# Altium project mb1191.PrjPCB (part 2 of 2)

## Sheet USB_OTG_HS.SchDoc: USB OTG HS PHY with Micro A-B connector
size A4; Date: 25-FEB-2015; Author: A.B; CompanyName: STMicroelectronics; Address1: 12, Rue Jules HOROWITZ; Address2: 38019 Grenoble; Address3: FRANCE; DocumentNumber: MB1191; Revision: B-02; SheetNumber: 11; SheetTotal: 14; Project: STM32F746G-DISCO
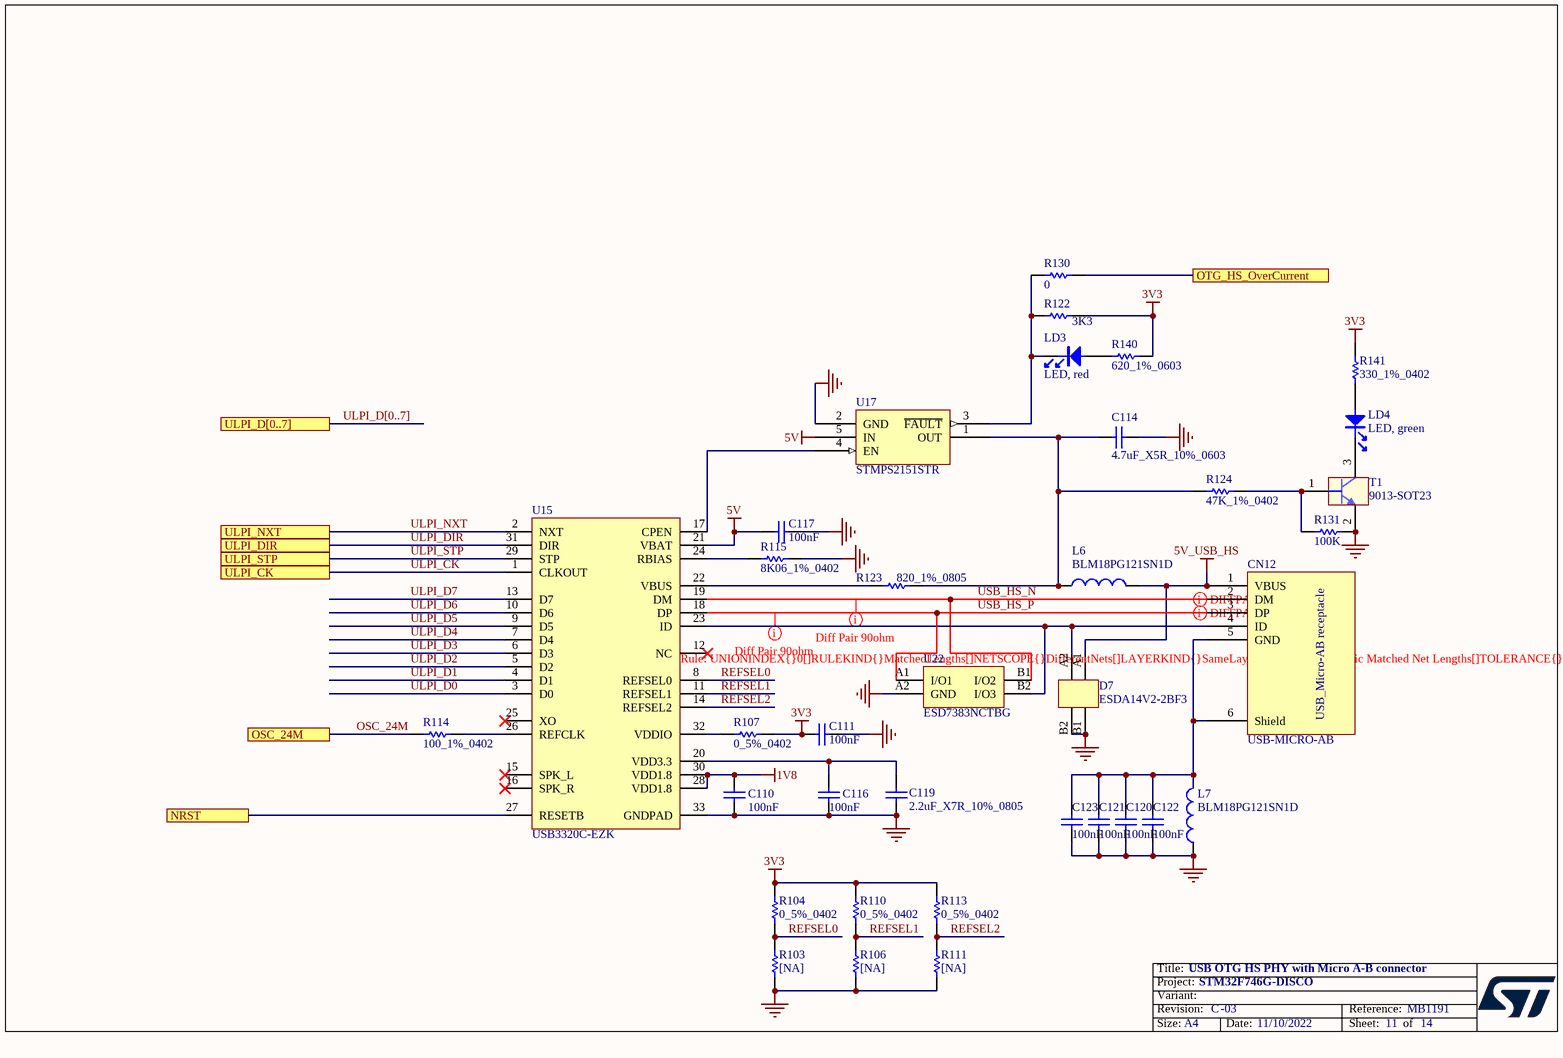
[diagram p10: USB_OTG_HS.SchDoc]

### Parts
C110  100nF  [0402C]
C111  100nF  [0402C]
C114  4.7uF_X5R_10%_0603  [0603C]
C116  100nF  [0402C]
C117  100nF  [0402C]
C119  2.2uF_X7R_10%_0805  [0805C]
C120  100nF  [0402C]
C121  100nF  [0402C]
C122  100nF  [0402C]
C123  100nF  [0402C]
CN12  USB-MICRO-AB  [USB-MICRO-AB]
D7  ESDA14V2-2BF3  [BGA4_1X1]
L6  BLM18PG121SN1D  [0603L]
L7  BLM18PG121SN1D  [0603L]
LD3  LED, red  [0603D]
LD4  LED, green  [0603D]
R103  [NA]  [0402R]
R104  0_5%_0402  [0402R]
R106  [NA]  [0402R]
R107  0_5%_0402  [0402R]
R110  0_5%_0402  [0402R]
R111  [NA]  [0402R]
R113  0_5%_0402  [0402R]
R114  100_1%_0402  [0402R]
R115  8K06_1%_0402  [0402R]
R122  3K3  [0402R]
R123  820_1%_0805  [0805R]
R124  47K_1%_0402  [0402R]
R130  0  [0402R]
R131  100K  [0402R]
R140  620_1%_0603  [0603R]
R141  330_1%_0402  [0402R]
T1  9013-SOT23  [SOT23]
U15  USB3320C-EZK  [QFN32_0R5_5X5]
U17  STMPS2151STR  [SOT23-5L]
U22  ESD7383NCTBG  [ESD_WLCSP4_CASE-567CB_0P80X0P80_P040]

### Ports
NRST, OSC_24M, OTG_HS_OverCurrent, ULPI_CK, ULPI_D[0..7], ULPI_DIR, ULPI_NXT, ULPI_STP

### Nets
1V8: C110.2 U15.28(VDD1.8) U15.30(VDD1.8)
3V3: C111.1 R104.2 R107.2 R110.2 R113.2 R122.1 R140.2 R141.2
5V: C117.1 U15.21(VBAT) U17.5(IN)
5V_USB_HS: CN12.1(VBUS) D7.A1 L6.2
GND: C110.1 C111.2 C114.2 C116.1 C117.2 C119.1 C120.1 C121.1 C122.1 C123.1 D7.B1 D7.B2 L7.1 R103.1 R106.1 R111.1 R115.2 R131.2 T1.2(E) U15.33(GNDPAD) U17.2(GND) U22.A2(GND)
DCMI_NRST: U15.27(RESETB) ; port NRST
OSC_24M: R114.1 ; port OSC_24M
OTG_HS_OverCurrent: R130.2 ; port OTG_HS_OverCurrent
REFSEL0: R103.2 R104.1 U15.8(REFSEL0)
REFSEL1: R106.2 R110.1 U15.11(REFSEL1)
REFSEL2: R111.2 R113.1 U15.14(REFSEL2)
ULPI_CK: U15.1(CLKOUT) ; port ULPI_CK  [project net PA5]
ULPI_D0: U15.3(D0)  [project net PA3]
ULPI_D1: U15.4(D1)  [project net PB0]
ULPI_D2: U15.5(D2)  [project net PB1]
ULPI_D3: U15.6(D3)  [project net PB10]
ULPI_D4: U15.7(D4)  [project net PB11]
ULPI_D5: U15.9(D5)  [project net PB12]
ULPI_D6: U15.10(D6)  [project net PB13]
ULPI_D7: U15.13(D7)  [project net PB5]
ULPI_DIR: U15.31(DIR) ; port ULPI_DIR  [project net PC2]
ULPI_NXT: U15.2(NXT) ; port ULPI_NXT  [project net PH4]
ULPI_STP: U15.29(STP) ; port ULPI_STP  [project net PC0]
USB_HS_N: CN12.2(DM) U15.19(DM) U22.B1(I/O2)
USB_HS_P: CN12.3(DP) U15.18(DP) U22.A1(I/O1)
NetC114_1: C114.1 L6.1 R123.2 R124.1 U17.1(OUT)
NetC116_2: C116.2 C119.2 U15.20(VDD3.3)
NetC120_2: C120.2 C121.2 C122.2 C123.2 CN12.5(GND) CN12.6(Shield) L7.2
NetCN12_4: CN12.4(ID) D7.A2 U15.23(ID) U22.B2(I/O3)
NetLD3_1: LD3.1 R140.1
NetLD3_2: LD3.2 R122.2 R130.1 U17.3(~{FAULT})
NetLD4_1: LD4.1 R141.1
NetLD4_2: LD4.2 T1.3(C)
NetR107_1: R107.1 U15.32(VDDIO)
NetR114_2: R114.2 U15.26(REFCLK)
NetR115_1: R115.1 U15.24(RBIAS)
NetR123_1: R123.1 U15.22(VBUS)
NetR124_2: R124.2 R131.1 T1.1(B)
NetU15_17: U15.17(CPEN) U17.4(EN)

Not connected (* = marked no-connect by the designer): U15 12(NC)* 15(SPK_L)* 16(SPK_R)* 25(XO)*

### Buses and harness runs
bus ULPI_D[0..7] = port ULPI_D[0..7]

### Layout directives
differential pair: USB_HS_N, USB_HS_P
rule Matched Net Lengths [Tolerance = 150mil]: USB_HS_N, USB_HS_P

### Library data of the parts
C110 C111 C116 C117 C120-C123 = Cap_100nF_X7R_10%_0402: Capacitor,100nF,16V,X7R,10%,0402,YAGEO; Manuf_Part_1: CC0402KRX7R7BB104
C114 = Cap_4.7uF_X5R_10%_0603: Capacitor,4.7uF,16V, X5R,10%,0603,YAGEO; Manuf_Part_1: CC0603KRX5R7BB475; Order: CC0603KRX5R7BB105
C119 = Cap_2.2uF_X7R_10%_0805: Capacitor,2.2uF,16V, X7R,10%,0805,YAGEO; Manuf_Part_1: CC0805KKX7R7BB225
CN12 = USB-MICRO-AB: USB-MICRO-AB, 47590-0001, SMT, MOLEX; Ref St: xxxxxxx
D7 = ESDA14V2-2BF3: Quad bidirectional Transil array for ESD protection; Manuf_1: STM; ECCN_US/EU: EAR99/NEC; Provided: ST; Ref St: 9179040
L6 L7 = BEAD_120R_2A_0603: Bead,120R,2A,0603,BLM18PG121SN1D,MURATA; Manuf_Part_3: FCM1608KF-601T03; Manuf_2: TDK; Manuf_Part_2: MPZ1608S300A; Manuf_3: Tai-tech; Value: 100uH; Description_3: Bead,600R,350mA,0603,FCM1608KF-601T03,Tai-tech; Description_2: Bead,30R,5A,0603,MPZ1608S300A,TDK
LD3 = LED_red: LED, red, 0603; Manuf_1: everlight; Manuf_Part_1: 19-217/R6C-AL1M2VY/3T; ECCN_US/EU: EAR99/NEC
LD4 = LED_green: LED, green, 0603; Manuf_1: everlight; Manuf_Part_1: 19-213SYGC/S530-E2/TR8; ECCN_US/EU: EAR99/NEC
R103 R106 R111 = Res_NA_0402: Resistor,[NA],0402; Fitted: NO
R104 R107 R110 R113 = Res_0_5%_0402: Resistor,0,0402,5%,YAGEO; Manuf_Part_1: RC0402JR-070RL; Value: 0; Order: 2363467
R114 = Res_100_1%_0402: Resistor,100,0402,1%,YAGEO; Manuf_Part_1: RC0402FR-07100RL; Value: 100; Order: 9239111
R115 = Res_8K06_1%_0402: Resistor,8K06,0402,1%,YAGEO; Manuf_Part_1: RC0402FR-078K06L
R122 = Res_3K3_1%_0402: Resistor,3K3,0402,1%,YAGEO; Manuf_Part_1: RC0402FR-073K3L
R123 = Res_820_1%_0805: Resistor,820,0805,1%,YAGEO; Manuf_Part_1: RC0805FR-07820RL; Value: 820
R124 = Res_47K_1%_0402: Resistor,47K,0402,1%,YAGEO; Manuf_Part_1: RC0402FR-0747KL; Order: 9239430
R130 = Res_0_5%_0402: Resistor,0,0402,5%,YAGEO; Manuf_Part_1: RC0402JR-070RL; Order: 2363467
R131 = Res_100K_1%_0402: Resistor,100K,0402,1%,YAGEO; Manuf_Part_1: RT0402FRE07100KL
R140 = Res_620_1%_0603: Resistor,620,0603,1%,VISHAY; Manuf_Part_1: CRCW0603620RFKEA; Manuf_1: VISHAY DRALORIC; Value: 620; Order: 2122341
R141 = Res_330_1%_0402: Resistor,330,0402,1%,YAGEO; Manuf_Part_1: RC0402FR-07330RL; Value: 330
T1 = 9013-SOT23: NPN Bipolar Transistor; Manuf_1: NXP; Manuf_Part_1: BSR14; Order: 1081310; ECCN_US/EU: EAR99/NEC
U15 = USB3320C-EZK: USB3320C,  Hi-Speed USB Host, Device or OTG PHY with ULPI Low Pin Interface; Manuf_1: MICROCHIP; Manuf_Part_1: USB3320C-EZK-TR
U17 = STMPS2151STR: Enhanced single channel power switches; Manuf_1: STM; Provided: ST; ECCN_US/EU: EAR99/NEC; Ref St: xxxxxx
U22 = ESD7383NCTBG: 3-line low capacitance protection for high speed USB; Manuf_1: ON SEMICONDUCTOR; ECCN_US/EU: EAR99/NEC; provided: SUBCO

## Sheet STM32F7.SchDoc: STM32 MCU Connexion
size A3; Date: 25-FEB-2015; Author: A.B; CompanyName: STMicroelectronics; Address1: 12, Rue Jules HOROWITZ; Address2: 38019 Grenoble; Address3: FRANCE; DocumentNumber: MB1191; Revision: B-02; SheetNumber: 3; SheetTotal: 14; Project: STM32F746G-DISCO
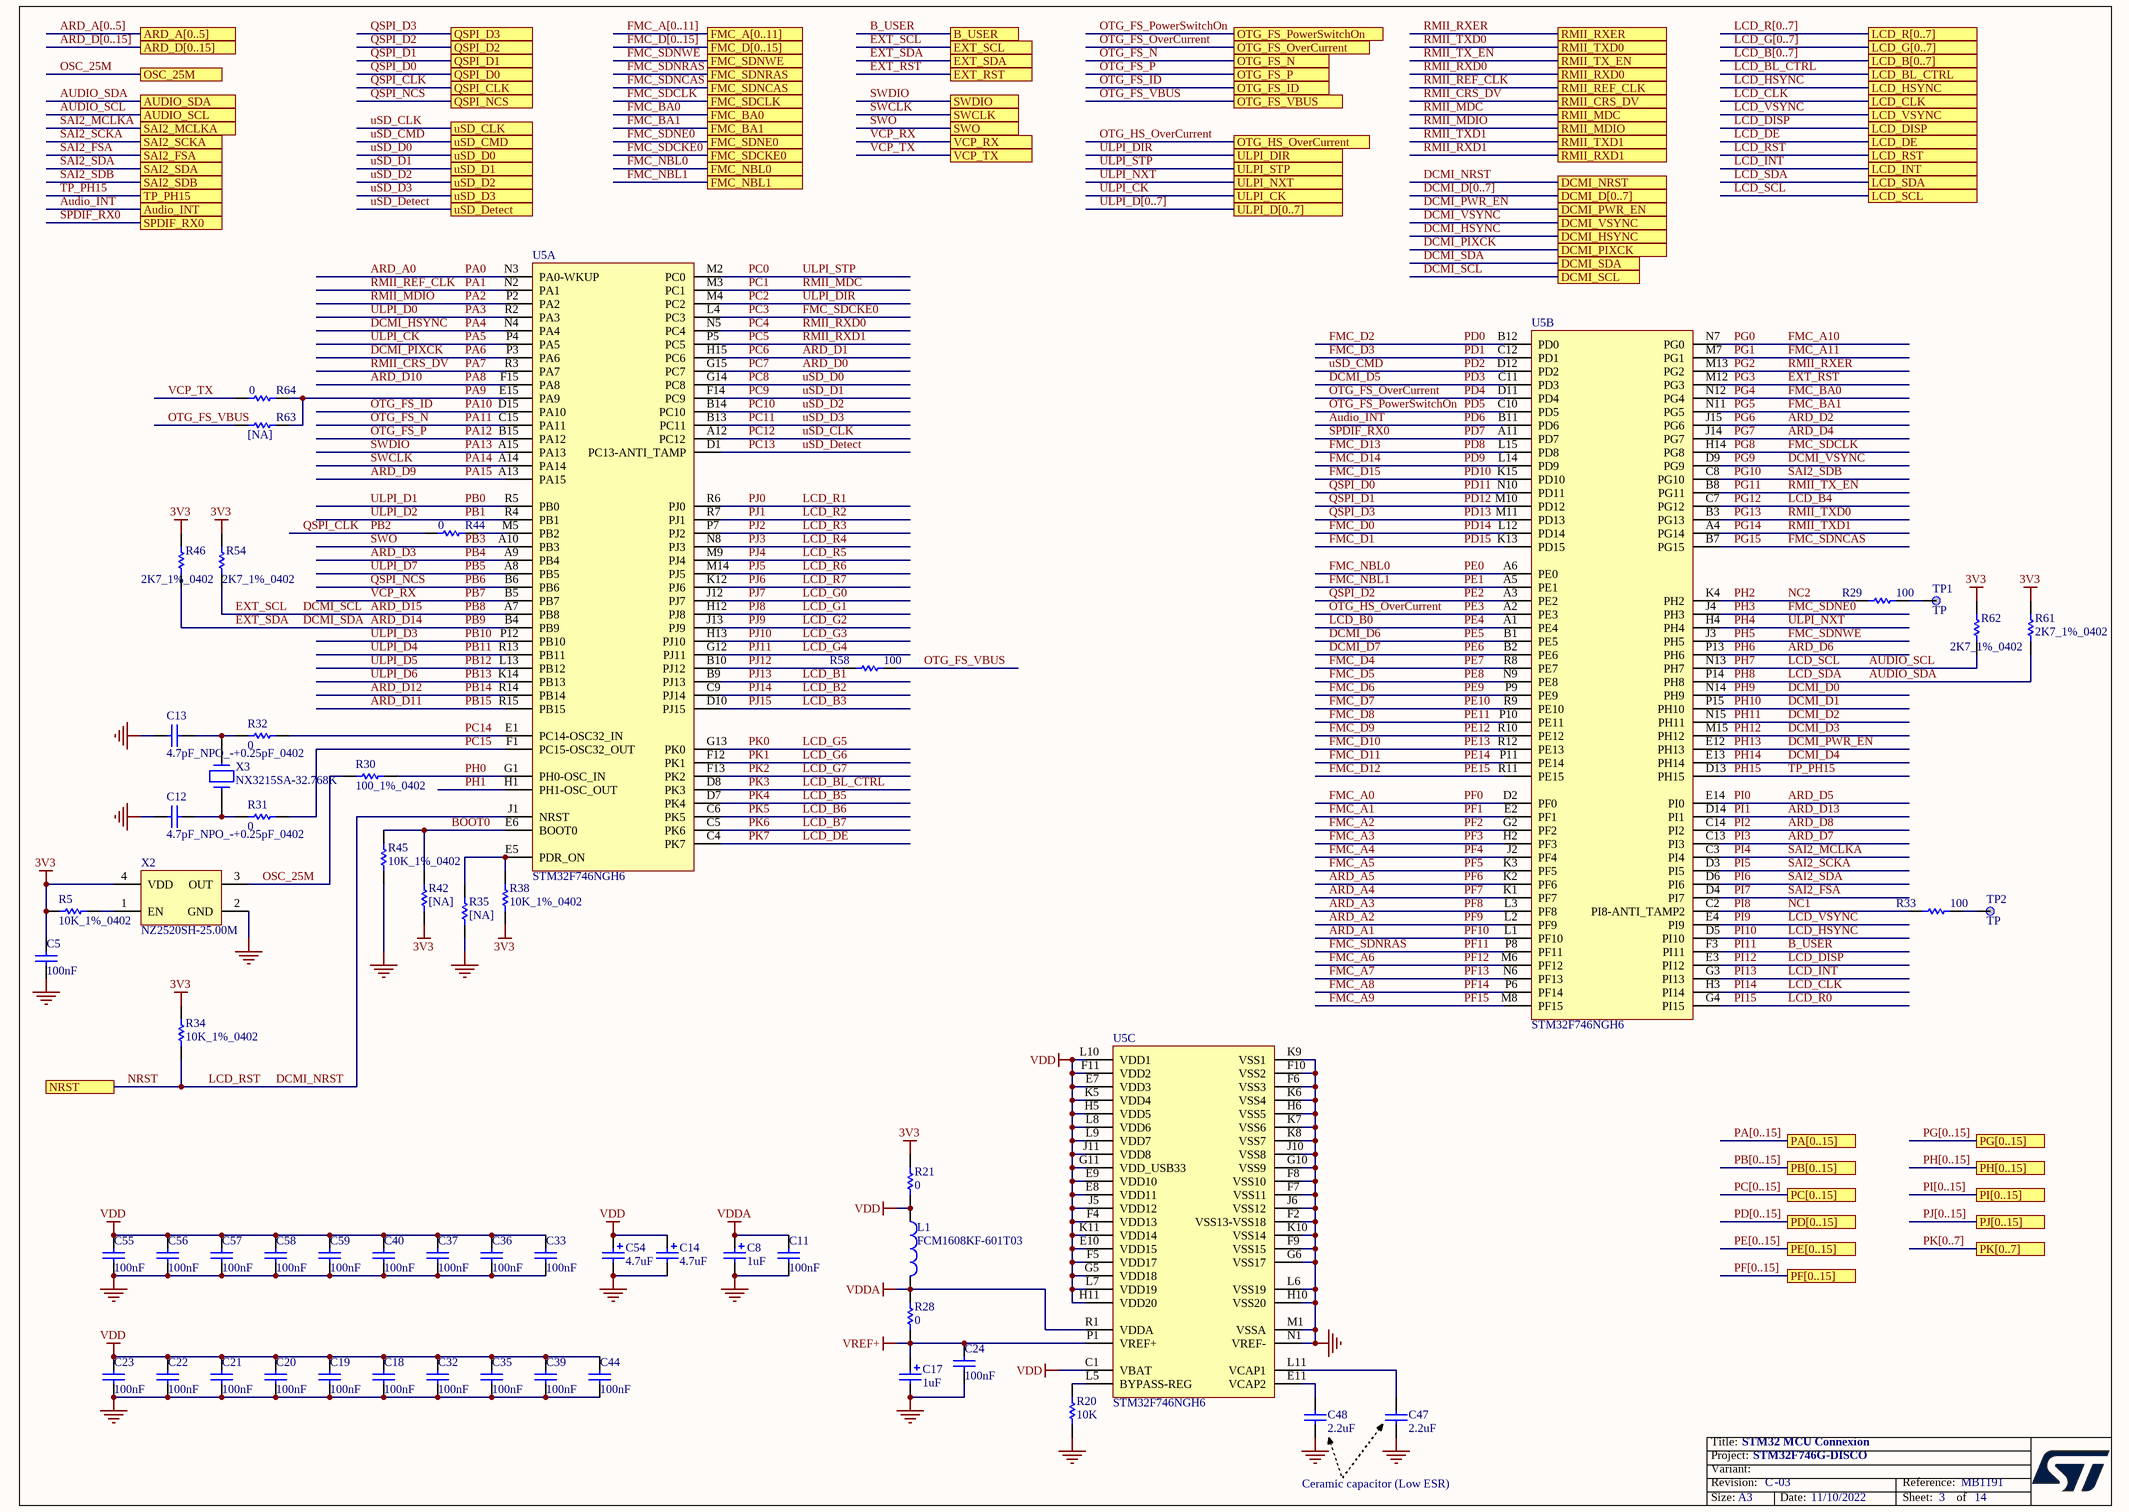
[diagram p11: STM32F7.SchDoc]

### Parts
C5  100nF  [0402C]
C8  1uF  [TAN-A]
C11  100nF  [0402C]
C12  4.7pF_NPO_-+0.25pF_0402  [0402C]
C13  4.7pF_NPO_-+0.25pF_0402  [0402C]
C14  4.7uF  [TAN-A]
C17  1uF  [TAN-A]
C18  100nF  [0402C]
C19  100nF  [0402C]
C20  100nF  [0402C]
C21  100nF  [0402C]
C22  100nF  [0402C]
C23  100nF  [0402C]
C24  100nF  [0402C]
C32  100nF  [0402C]
C33  100nF  [0402C]
C35  100nF  [0402C]
C36  100nF  [0402C]
C37  100nF  [0402C]
C39  100nF  [0402C]
C40  100nF  [0402C]
C44  100nF  [0402C]
C47  2.2uF  [1206C]
C48  2.2uF  [1206C]
C54  4.7uF  [TAN-A]
C55  100nF  [0402C]
C56  100nF  [0402C]
C57  100nF  [0402C]
C58  100nF  [0402C]
C59  100nF  [0402C]
L1  FCM1608KF-601T03  [0603L]
R5  10K_1%_0402  [0402R]
R20  10K  [0402R]
R21  0  [0603R-GS]
R28  0  [0603R-GS]
R29  100  [0402R]
R30  100_1%_0402  [0402R]
R31  0  [0402R]
R32  0  [0402R]
R33  100  [0402R]
R34  10K_1%_0402  [0402R]
R35  [NA]  [0402R]
R38  10K_1%_0402  [0402R]
R42  [NA]  [0402R]
R44  0  [0402R]
R45  10K_1%_0402  [0402R]
R46  2K7_1%_0402  [0402R]
R54  2K7_1%_0402  [0402R]
R58  100  [0402R]
R61  2K7_1%_0402  [0402R]
R62  2K7_1%_0402  [0402R]
R63  [NA]  [0402R]
R64  0  [0402R]
TP1  TP  [SMDTEST-1MM]
TP2  TP  [SMDTEST-1MM]
U5  STM32F746NGH6  [BGA216_0R8_13X13_SKT]  (parts A,B,C of 3)
X2  NZ2520SH-25.00M  [NZ2520SH_4P]
X3  NX3215SA-32.768K  [XTAL_2SM_3R2X1R5]

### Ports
ARD_A[0..5], ARD_D[0..15], Audio_INT, AUDIO_SCL, AUDIO_SDA, B_USER, DCMI_D[0..7], DCMI_HSYNC, DCMI_NRST, DCMI_PIXCK, DCMI_PWR_EN, DCMI_SCL, DCMI_SDA, DCMI_VSYNC, EXT_RST, EXT_SCL, EXT_SDA, FMC_A[0..11], FMC_BA0, FMC_BA1, FMC_D[0..15], FMC_NBL0, FMC_NBL1, FMC_SDCKE0, FMC_SDCLK, FMC_SDNCAS, FMC_SDNE0, FMC_SDNRAS, FMC_SDNWE, LCD_B[0..7], LCD_BL_CTRL, LCD_CLK, LCD_DE, LCD_DISP, LCD_G[0..7], LCD_HSYNC, LCD_INT, LCD_R[0..7], LCD_RST, LCD_SCL, LCD_SDA, LCD_VSYNC, NRST, OSC_25M, OTG_FS_ID, OTG_FS_N, OTG_FS_OverCurrent, OTG_FS_P, OTG_FS_PowerSwitchOn, OTG_FS_VBUS, OTG_HS_OverCurrent, PA[0..15], PB[0..15], PC[0..15], PD[0..15], PE[0..15], PF[0..15], PG[0..15], PH[0..15], PI[0..15], PJ[0..15], PK[0..7], QSPI_CLK, QSPI_D0, QSPI_D1, QSPI_D2, QSPI_D3, QSPI_NCS, RMII_CRS_DV, RMII_MDC, RMII_MDIO, RMII_REF_CLK, RMII_RXD0, RMII_RXD1, RMII_RXER, RMII_TX_EN, RMII_TXD0, RMII_TXD1, SAI2_FSA, SAI2_MCLKA, SAI2_SCKA, SAI2_SDA, SAI2_SDB, SPDIF_RX0, SWCLK, SWDIO, SWO, TP_PH15, ULPI_CK, ULPI_D[0..7], ULPI_DIR, ULPI_NXT, ULPI_STP, uSD_CLK, uSD_CMD, uSD_D0, uSD_D1, uSD_D2, uSD_D3, uSD_Detect, VCP_RX, VCP_TX

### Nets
3V3: C5.2 R5.1 R21.2 R34.2 R38.1 R42.1 R46.2 R54.2 R61.2 R62.2 X2.4(VDD)
GND: C5.1 C8.2 C11.1 C12.1 C13.1 C14.2 C17.2 C18.1 C19.1 C20.1 C21.1 C22.1 C23.1 C24.1 C32.1 C33.1 C35.1 C36.1 C37.1 C39.1 C40.1 C44.1 C47.1 C48.1 C54.2 C55.1 C56.1 C57.1 C58.1 C59.1 R20.1 R35.1 R45.1 U5.F2(VSS13-VSS18) U5.F6(VSS3) U5.F7(VSS11) U5.F8(VSS10) U5.F9(VSS15) U5.F10(VSS2) U5.G6(VSS17) U5.G10(VSS9) U5.H6(VSS5) U5.H10(VSS20) U5.J6(VSS12) U5.J10(VSS8) U5.K6(VSS4) U5.K7(VSS6) U5.K8(VSS7) U5.K9(VSS1) U5.K10(VSS14) U5.L6(VSS19) U5.M1(VSSA) U5.N1(VREF-) X2.2(GND)
VDD: C14.1 C18.2 C19.2 C20.2 C21.2 C22.2 C23.2 C32.2 C33.2 C35.2 C36.2 C37.2 C39.2 C40.2 C44.2 C54.1 C55.2 C56.2 C57.2 C58.2 C59.2 L1.1 R21.1 U5.C1(VBAT) U5.E7(VDD3) U5.E8(VDD11) U5.E9(VDD10) U5.E10(VDD15) U5.F4(VDD13) U5.F5(VDD17) U5.F11(VDD2) U5.G5(VDD18) U5.G11(VDD_USB33) U5.H5(VDD5) U5.H11(VDD20) U5.J5(VDD12) U5.J11(VDD8) U5.K5(VDD4) U5.K11(VDD14) U5.L7(VDD19) U5.L8(VDD6) U5.L9(VDD7) U5.L10(VDD1)
VDDA: C8.1 C11.2 L1.2 R28.1 U5.R1(VDDA)
VREF+: C17.1 C24.2 R28.2 U5.P1(VREF+)
ARD_A0: U5.N3(PA0-WKUP)  [also labelled PA0]
ARD_A1: U5.L1(PF10)  [also labelled PF10]
ARD_A2: U5.L2(PF9)  [also labelled PF9]
ARD_A3: U5.L3(PF8)  [also labelled PF8]
ARD_A4: U5.K1(PF7)  [also labelled PF7]
ARD_A5: U5.K2(PF6)  [also labelled PF6]
ARD_D0: U5.G15(PC7)  [also labelled PC7]
ARD_D1: U5.H15(PC6)  [also labelled PC6]
ARD_D2: U5.J15(PG6)  [also labelled PG6]
ARD_D3: U5.A9(PB4)  [also labelled PB4]
ARD_D4: U5.J14(PG7)  [also labelled PG7]
ARD_D5: U5.E14(PI0)  [also labelled PI0]
ARD_D6: U5.P13(PH6)  [also labelled PH6]
ARD_D7: U5.C13(PI3)  [also labelled PI3]
ARD_D8: U5.C14(PI2)  [also labelled PI2]
ARD_D9: U5.A13(PA15)  [also labelled PA15]
ARD_D10: U5.F15(PA8)  [also labelled PA8]
ARD_D11: U5.R15(PB15)  [also labelled PB15]
ARD_D12: U5.R14(PB14)  [also labelled PB14]
ARD_D13: U5.D14(PI1)  [also labelled PI1]
ARD_D14: R46.1 U5.B4(PB9) ; port DCMI_SDA, port EXT_SDA  [also labelled DCMI_SDA, EXT_SDA, PB9]
ARD_D15: R54.1 U5.A7(PB8) ; port DCMI_SCL, port EXT_SCL  [also labelled DCMI_SCL, EXT_SCL, PB8]
Audio_INT: U5.B11(PD6) ; port Audio_INT  [also labelled PD6]
AUDIO_SCL: R62.1 U5.N13(PH7) ; port LCD_SCL, port AUDIO_SCL  [also labelled LCD_SCL, PH7]
AUDIO_SDA: R61.1 U5.P14(PH8) ; port LCD_SDA, port AUDIO_SDA  [also labelled LCD_SDA, PH8]
B_USER: U5.F3(PI11) ; port B_USER  [also labelled PI11]
BOOT0: R42.2 R45.2 U5.E6(BOOT0)
DCMI_D0: U5.N14(PH9)  [also labelled PH9]
DCMI_D1: U5.P15(PH10)  [also labelled PH10]
DCMI_D2: U5.N15(PH11)  [also labelled PH11]
DCMI_D3: U5.M15(PH12)  [also labelled PH12]
DCMI_D4: U5.E13(PH14)  [also labelled PH14]
DCMI_D5: U5.C11(PD3)  [also labelled PD3]
DCMI_D6: U5.B1(PE5)  [also labelled PE5]
DCMI_D7: U5.B2(PE6)  [also labelled PE6]
DCMI_HSYNC: U5.N4(PA4) ; port DCMI_HSYNC  [also labelled PA4]
DCMI_NRST: R34.1 U5.J1(NRST) ; port NRST, port LCD_RST, port DCMI_NRST  [also labelled LCD_RST, NRST]
DCMI_PIXCK: U5.P3(PA6) ; port DCMI_PIXCK  [also labelled PA6]
DCMI_PWR_EN: U5.E12(PH13) ; port DCMI_PWR_EN  [also labelled PH13]
DCMI_VSYNC: U5.D9(PG9) ; port DCMI_VSYNC  [also labelled PG9]
EXT_RST: U5.M12(PG3) ; port EXT_RST  [also labelled PG3]
FMC_A0: U5.D2(PF0)  [also labelled PF0]
FMC_A1: U5.E2(PF1)  [also labelled PF1]
FMC_A2: U5.G2(PF2)  [also labelled PF2]
FMC_A3: U5.H2(PF3)  [also labelled PF3]
FMC_A4: U5.J2(PF4)  [also labelled PF4]
FMC_A5: U5.K3(PF5)  [also labelled PF5]
FMC_A6: U5.M6(PF12)  [also labelled PF12]
FMC_A7: U5.N6(PF13)  [also labelled PF13]
FMC_A8: U5.P6(PF14)  [also labelled PF14]
FMC_A9: U5.M8(PF15)  [also labelled PF15]
FMC_A10: U5.N7(PG0)  [also labelled PG0]
FMC_A11: U5.M7(PG1)  [also labelled PG1]
FMC_BA0: U5.N12(PG4) ; port FMC_BA0  [also labelled PG4]
FMC_BA1: U5.N11(PG5) ; port FMC_BA1  [also labelled PG5]
FMC_D0: U5.L12(PD14)  [also labelled PD14]
FMC_D1: U5.K13(PD15)  [also labelled PD15]
FMC_D2: U5.B12(PD0)  [also labelled PD0]
FMC_D3: U5.C12(PD1)  [also labelled PD1]
FMC_D4: U5.R8(PE7)  [also labelled PE7]
FMC_D5: U5.N9(PE8)  [also labelled PE8]
FMC_D6: U5.P9(PE9)  [also labelled PE9]
FMC_D7: U5.R9(PE10)  [also labelled PE10]
FMC_D8: U5.P10(PE11)  [also labelled PE11]
FMC_D9: U5.R10(PE12)  [also labelled PE12]
FMC_D10: U5.R12(PE13)  [also labelled PE13]
FMC_D11: U5.P11(PE14)  [also labelled PE14]
FMC_D12: U5.R11(PE15)  [also labelled PE15]
FMC_D13: U5.L15(PD8)  [also labelled PD8]
FMC_D14: U5.L14(PD9)  [also labelled PD9]
FMC_D15: U5.K15(PD10)  [also labelled PD10]
FMC_NBL0: U5.A6(PE0) ; port FMC_NBL0  [also labelled PE0]
FMC_NBL1: U5.A5(PE1) ; port FMC_NBL1  [also labelled PE1]
FMC_SDCKE0: U5.L4(PC3) ; port FMC_SDCKE0  [also labelled PC3]
FMC_SDCLK: U5.H14(PG8) ; port FMC_SDCLK  [also labelled PG8]
FMC_SDNCAS: U5.B7(PG15) ; port FMC_SDNCAS  [also labelled PG15]
FMC_SDNE0: U5.J4(PH3) ; port FMC_SDNE0  [also labelled PH3]
FMC_SDNRAS: U5.P8(PF11) ; port FMC_SDNRAS  [also labelled PF11]
FMC_SDNWE: U5.J3(PH5) ; port FMC_SDNWE  [also labelled PH5]
LCD_B0: U5.A1(PE4)  [also labelled PE4]
LCD_B1: U5.B9(PJ13)  [also labelled PJ13]
LCD_B2: U5.C9(PJ14)  [also labelled PJ14]
LCD_B3: U5.D10(PJ15)  [also labelled PJ15]
LCD_B4: U5.C7(PG12)  [also labelled PG12]
LCD_B5: U5.D7(PK4)  [also labelled PK4]
LCD_B6: U5.C6(PK5)  [also labelled PK5]
LCD_B7: U5.C5(PK6)  [also labelled PK6]
LCD_BL_CTRL: U5.D8(PK3) ; port LCD_BL_CTRL  [also labelled PK3]
LCD_CLK: U5.H3(PI14) ; port LCD_CLK  [also labelled PI14]
LCD_DE: U5.C4(PK7) ; port LCD_DE  [also labelled PK7]
LCD_DISP: U5.E3(PI12) ; port LCD_DISP  [also labelled PI12]
LCD_G0: U5.J12(PJ7)  [also labelled PJ7]
LCD_G1: U5.H12(PJ8)  [also labelled PJ8]
LCD_G2: U5.J13(PJ9)  [also labelled PJ9]
LCD_G3: U5.H13(PJ10)  [also labelled PJ10]
LCD_G4: U5.G12(PJ11)  [also labelled PJ11]
LCD_G5: U5.G13(PK0)  [also labelled PK0]
LCD_G6: U5.F12(PK1)  [also labelled PK1]
LCD_G7: U5.F13(PK2)  [also labelled PK2]
LCD_HSYNC: U5.D5(PI10) ; port LCD_HSYNC  [also labelled PI10]
LCD_INT: U5.G3(PI13) ; port LCD_INT  [also labelled PI13]
LCD_R0: U5.G4(PI15)  [also labelled PI15]
LCD_R1: U5.R6(PJ0)  [also labelled PJ0]
LCD_R2: U5.R7(PJ1)  [also labelled PJ1]
LCD_R3: U5.P7(PJ2)  [also labelled PJ2]
LCD_R4: U5.N8(PJ3)  [also labelled PJ3]
LCD_R5: U5.M9(PJ4)  [also labelled PJ4]
LCD_R6: U5.M14(PJ5)  [also labelled PJ5]
LCD_R7: U5.K12(PJ6)  [also labelled PJ6]
LCD_VSYNC: U5.E4(PI9) ; port LCD_VSYNC  [also labelled PI9]
NC1: R33.1 U5.C2(PI8-ANTI_TAMP2)  [also labelled PI8]
NC2: R29.1 U5.K4(PH2)  [also labelled PH2]
OSC_25M: R30.1 X2.3(OUT) ; port OSC_25M
OTG_FS_ID: U5.D15(PA10) ; port OTG_FS_ID  [also labelled PA10]
OTG_FS_N: U5.C15(PA11) ; port OTG_FS_N  [also labelled PA11]
OTG_FS_OverCurrent: U5.D11(PD4) ; port OTG_FS_OverCurrent  [also labelled PD4]
OTG_FS_P: U5.B15(PA12) ; port OTG_FS_P  [also labelled PA12]
OTG_FS_PowerSwitchOn: U5.C10(PD5) ; port OTG_FS_PowerSwitchOn  [also labelled PD5]
OTG_FS_VBUS: R58.2 R63.1 ; port OTG_FS_VBUS
OTG_HS_OverCurrent: U5.A2(PE3) ; port OTG_HS_OverCurrent  [also labelled PE3]
PA1: U5.N2(PA1) ; port RMII_REF_CLK  [also labelled RMII_REF_CLK]
PA2: U5.P2(PA2) ; port RMII_MDIO  [also labelled RMII_MDIO]
PA3: U5.R2(PA3)  [also labelled ULPI_D0]
PA5: U5.P4(PA5) ; port ULPI_CK  [also labelled ULPI_CK]
PA7: U5.R3(PA7) ; port RMII_CRS_DV  [also labelled RMII_CRS_DV]
PA9: R63.2 R64.2 U5.E15(PA9)
PA13: U5.A15(PA13) ; port SWDIO  [also labelled SWDIO]
PA14: U5.A14(PA14) ; port SWCLK  [also labelled SWCLK]
PB0: U5.R5(PB0)  [also labelled ULPI_D1]
PB1: U5.R4(PB1)  [also labelled ULPI_D2]
PB2: R44.1 ; port QSPI_CLK  [also labelled QSPI_CLK]
PB3: U5.A10(PB3) ; port SWO  [also labelled SWO]
PB5: U5.A8(PB5)  [also labelled ULPI_D7]
PB6: U5.B6(PB6) ; port QSPI_NCS  [also labelled QSPI_NCS]
PB7: U5.B5(PB7) ; port VCP_RX  [also labelled VCP_RX]
PB10: U5.P12(PB10)  [also labelled ULPI_D3]
PB11: U5.R13(PB11)  [also labelled ULPI_D4]
PB12: U5.L13(PB12)  [also labelled ULPI_D5]
PB13: U5.K14(PB13)  [also labelled ULPI_D6]
PC0: U5.M2(PC0) ; port ULPI_STP  [also labelled ULPI_STP]
PC1: U5.M3(PC1) ; port RMII_MDC  [also labelled RMII_MDC]
PC2: U5.M4(PC2) ; port ULPI_DIR  [also labelled ULPI_DIR]
PC4: U5.N5(PC4) ; port RMII_RXD0  [also labelled RMII_RXD0]
PC5: U5.P5(PC5) ; port RMII_RXD1  [also labelled RMII_RXD1]
PC8: U5.G14(PC8) ; port uSD_D0  [also labelled uSD_D0]
PC9: U5.F14(PC9) ; port uSD_D1  [also labelled uSD_D1]
PC10: U5.B14(PC10) ; port uSD_D2  [also labelled uSD_D2]
PC11: U5.B13(PC11) ; port uSD_D3  [also labelled uSD_D3]
PC12: U5.A12(PC12) ; port uSD_CLK  [also labelled uSD_CLK]
PC13: U5.D1(PC13-ANTI_TAMP) ; port uSD_Detect  [also labelled uSD_Detect]
PC14: R32.2 U5.E1(PC14-OSC32_IN)
PC15: R31.2 U5.F1(PC15-OSC32_OUT)
PD2: U5.D12(PD2) ; port uSD_CMD  [also labelled uSD_CMD]
PD7: U5.A11(PD7) ; port SPDIF_RX0  [also labelled SPDIF_RX0]
PD11: U5.N10(PD11) ; port QSPI_D0  [also labelled QSPI_D0]
PD12: U5.M10(PD12) ; port QSPI_D1  [also labelled QSPI_D1]
PD13: U5.M11(PD13) ; port QSPI_D3  [also labelled QSPI_D3]
PE2: U5.A3(PE2) ; port QSPI_D2  [also labelled QSPI_D2]
PG2: U5.M13(PG2) ; port RMII_RXER  [also labelled RMII_RXER]
PG10: U5.C8(PG10) ; port SAI2_SDB  [also labelled SAI2_SDB]
PG11: U5.B8(PG11) ; port RMII_TX_EN  [also labelled RMII_TX_EN]
PG13: U5.B3(PG13) ; port RMII_TXD0  [also labelled RMII_TXD0]
PG14: U5.A4(PG14) ; port RMII_TXD1  [also labelled RMII_TXD1]
PH0: R30.2 U5.G1(PH0-OSC_IN)
PH1: U5.H1(PH1-OSC_OUT)
PH4: U5.H4(PH4) ; port ULPI_NXT  [also labelled ULPI_NXT]
PH15: U5.D13(PH15) ; port TP_PH15  [also labelled TP_PH15]
PI4: U5.C3(PI4) ; port SAI2_MCLKA  [also labelled SAI2_MCLKA]
PI5: U5.D3(PI5) ; port SAI2_SCKA  [also labelled SAI2_SCKA]
PI6: U5.D6(PI6) ; port SAI2_SDA  [also labelled SAI2_SDA]
PI7: U5.D4(PI7) ; port SAI2_FSA  [also labelled SAI2_FSA]
PJ12: R58.1 U5.B10(PJ12)
VCP_TX: R64.1 ; port VCP_TX
NetC12_2: C12.2 R31.1 X3.2
NetC13_2: C13.2 R32.1 X3.1
NetC47_2: C47.2 U5.L11(VCAP1)
NetC48_2: C48.2 U5.E11(VCAP2)
NetR5_2: R5.2 X2.1(EN)
NetR20_2: R20.2 U5.L5(BYPASS-REG)
NetR29_2: R29.2 TP1.1
NetR33_2: R33.2 TP2.1
NetR35_2: R35.2 R38.2 U5.E5(PDR_ON)
NetR44_2: R44.2 U5.M5(PB2)

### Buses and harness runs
bus ARD_A[0..5] = port ARD_A[0..5]
bus ARD_D[0..15] = port ARD_D[0..15]
bus DCMI_D[0..7] = port DCMI_D[0..7]
bus FMC_A[0..11] = port FMC_A[0..11]
bus FMC_D[0..15] = port FMC_D[0..15]
bus LCD_B[0..7] = port LCD_B[0..7]
bus LCD_G[0..7] = port LCD_G[0..7]
bus LCD_R[0..7] = port LCD_R[0..7]
bus PA[0..15] = port PA[0..15]
bus PB[0..15] = port PB[0..15]
bus PC[0..15] = port PC[0..15]
bus PD[0..15] = port PD[0..15]
bus PE[0..15] = port PE[0..15]
bus PF[0..15] = port PF[0..15]
bus PG[0..15] = port PG[0..15]
bus PH[0..15] = port PH[0..15]
bus PI[0..15] = port PI[0..15]
bus PJ[0..15] = port PJ[0..15]
bus PK[0..7] = port PK[0..7]
bus ULPI_D[0..7] = port ULPI_D[0..7]

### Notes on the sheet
- Ceramic capacitor (Low ESR)

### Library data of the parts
C5 C11 C18-C24 C32 C33 C35-C37 C39 C40 C44 C55-C59 = Cap_100nF_X7R_10%_0402: as C110 on sheet USB_OTG_HS
C8 C17 = Cap_1uF_POL_10%_TANA: Polarized Capacitor,1uF,16V,10%,typeA,AVX; Manuf_Part_1: TAJA105K016R
C12 C13 = Cap_4.7pF_NPO_-+0.25pF_0402: Capacitor, 4.7pF, 50V, NPO, -+0.25pF, 0402, YAGEO; Manuf_Part_1: CC0402CRNPO9BN4R7; Order: 311-1367-2-ND
C14 C54 = Cap_4.7uF_POL_10%_TANA: Polarized Capacitor,4.7uF,16V,10%,typeA,AVX; Manuf_Part_1: TAJA475K016R
C47 C48 = Cap_2.2uF_X7R_10%_1206: Capacitor,2.2uF,16V, X7R,10%,1206,YAGEO; Manuf_Part_1: CC1206KKX7R7BB225; Manuf_Part_2: C1206C225K4RAC; Manuf_2: KEMET
L1 = BEAD_600R_350MA_0603: Bead,600R,350mA,0603,FCM1608KF-601T03,Tai-tech; Manuf_2: TDK; Manuf_Part_2: MPZ1608S300A; Manuf_Part_3: BLM18PG121SN1D; Manuf_3: MURATA; Value: 100uH; Description_2: Bead,30R,5A,0603,MPZ1608S300A,TDK; Description_3: Bead,120R,2A,0603,BLM18PG121SN1D,MURATA
R5 R20 R34 R38 R45 = Res_10K_1%_0402: Resistor,10K,0402,1%,YAGEO; Manuf_Part_1: RC0402FR-0710KL
R21 R28 = Res_0_5%_0603: Resistor,0,0603,5%,YAGEO; Manuf_Part_1: RC0603JR-070RL; Order: 2363481
R29 R33 R58 = Res_100_1%_0402: Resistor,100,0402,1%,YAGEO; Manuf_Part_1: RC0402FR-07100RL; Order: 9239111
R30 = Res_100_1%_0402: as R114 on sheet USB_OTG_HS
R31 R32 R44 R64 = Res_0_5%_0402: as R130 on sheet USB_OTG_HS
R35 R42 R63 = Res_NA_0402: Resistor,[NA],0402; Fitted: NO
R46 R54 R61 R62 = Res_2K7_1%_0402: Resistor,2K7,0402,1%,YAGEO; Manuf_Part_1: RC0402FR-072K7L
TP1 TP2 = TP: Test Point
U5 = STM32F746NGH6U: STM32F746NGH6 (STM32F7 Birdie) TBGA216; Manuf_1: STM; ECCN_US/EU: 3A991A2/NEC; Ref St: 9175176; Provided: ST
X2 = OSC_25M_NZ2520SB: Oscillator 25.00Mhz, -+50PPM, 3.3V, Temp -55 to +125°C; Manuf_Part_1: NZ2520SH 25MHz END4869C; Manuf_1: NDK; ECCN_US/EU: EAR99/NEC; Provided: ST
X3 = XTAL_32K_NX3215SA: Crystal 32.768kHz, 6pF, -+20PPM, R=50K, SMD; Manuf_1: NDK; Manuf_Part_1: NX3215SA 32.768KHz EXS00A-MU00525; ECCN_US/EU: EAR99/NEC; Ref St: 9157034; NDK Ref: X3101802; Provided: ST

## Sheet Ethernet.SchDoc: Ethernet PHY with RJ45 connector
size A4; Date: 25-FEB-2015; Author: A.B; CompanyName: STMicroelectronics; Address1: 12, Rue Jules HOROWITZ; Address2: 38019 Grenoble; Address3: FRANCE; DocumentNumber: MB1191; Revision: B-02; SheetNumber: 12; SheetTotal: 14; Project: STM32F746G-DISCO
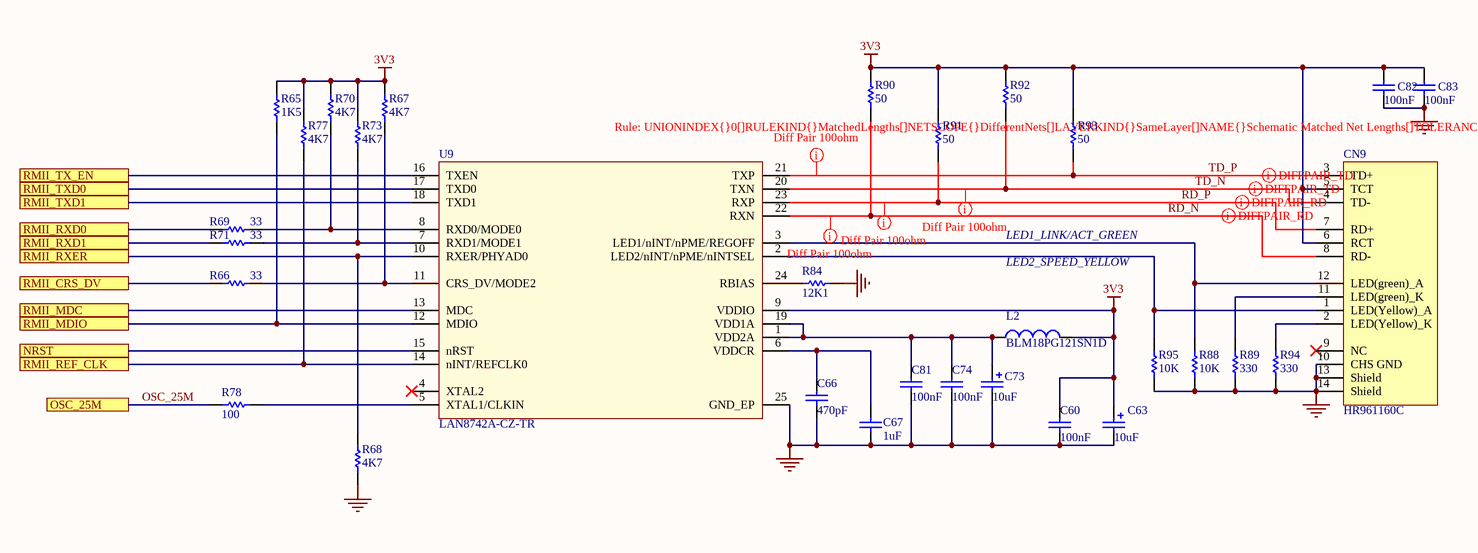
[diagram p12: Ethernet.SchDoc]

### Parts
C60  100nF  [0402C]
C63  10uF  [TAN-A]
C66  470pF  [0402C]
C67  1uF  [0603C]
C73  10uF  [TAN-A]
C74  100nF  [0402C]
C81  100nF  [0402C]
C82  100nF  [0402C]
C83  100nF  [0402C]
CN9  HR961160C  [RJ45_HR961160C]
L2  BLM18PG121SN1D  [0603L]
R65  1K5  [0402R]
R66  33  [0402R]
R67  4K7  [0402R]
R68  4K7  [0402R]
R69  33  [0402R]
R70  4K7  [0402R]
R71  33  [0402R]
R73  4K7  [0402R]
R77  4K7  [0402R]
R78  100  [0402R]
R84  12K1  [0603R]
R88  10K  [0402R]
R89  330  [0402R]
R90  50  [0402R]
R91  50  [0402R]
R92  50  [0402R]
R93  50  [0402R]
R94  330  [0402R]
R95  10K  [0402R]
U9  LAN8742A-CZ-TR  [QFN24_0R5_4X4]

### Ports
NRST, OSC_25M, RMII_CRS_DV, RMII_MDC, RMII_MDIO, RMII_REF_CLK, RMII_RXD0, RMII_RXD1, RMII_RXER, RMII_TX_EN, RMII_TXD0, RMII_TXD1

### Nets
3V3: C60.2 C63.1 C82.2 C83.2 CN9.5(TCT) CN9.6(RCT) L2.2 R65.2 R67.2 R70.2 R73.2 R77.2 R90.1 R91.1 R92.1 R93.1 U9.9(VDDIO)
GND: C60.1 C63.2 C66.1 C67.1 C73.2 C74.1 C81.1 C82.1 C83.1 CN9.10(CHS_GND) CN9.13(Shield) CN9.14(Shield) R68.1 R84.2 R88.1 R89.1 R94.1 R95.1 U9.25(GND_EP)
DCMI_NRST: U9.15(nRST) ; port NRST
OSC_25M: R78.1 ; port OSC_25M
PA1: R77.1 U9.14(nINT/REFCLK0) ; port RMII_REF_CLK
PA2: R65.1 U9.12(MDIO) ; port RMII_MDIO
PA7: R66.2 ; port RMII_CRS_DV
PC1: U9.13(MDC) ; port RMII_MDC
PC4: R69.2 ; port RMII_RXD0
PC5: R71.2 ; port RMII_RXD1
PG2: R68.2 U9.10(RXER/PHYAD0) ; port RMII_RXER
PG11: U9.16(TXEN) ; port RMII_TX_EN
PG13: U9.17(TXD0) ; port RMII_TXD0
PG14: U9.18(TXD1) ; port RMII_TXD1
RD_N: CN9.8(RD-) R90.2 U9.22(RXN)
RD_P: CN9.7(RD+) R91.2 U9.23(RXP)
TD_N: CN9.4(TD-) R92.2 U9.20(TXN)
TD_P: CN9.3(TD+) R93.2 U9.21(TXP)
NetC66_2: C66.2 C67.2 U9.6(VDDCR)
NetC73_1: C73.1 C74.2 C81.2 L2.1 U9.1(VDD2A) U9.19(VDD1A)
NetCN9_1: CN9.1(LED(Yellow)_A) R95.2 U9.2(LED2/nINT/nPME/nINTSEL)
NetCN9_2: CN9.2(LED(Yellow)_K) R94.2
NetCN9_11: CN9.11(LED(green)_K) R89.2
NetCN9_12: CN9.12(LED(green)_A) R88.2 U9.3(LED1/nINT/nPME/REGOFF)
NetR66_1: R66.1 R67.1 U9.11(CRS_DV/MODE2)
NetR69_1: R69.1 R70.1 U9.8(RXD0/MODE0)
NetR71_1: R71.1 R73.1 U9.7(RXD1/MODE1)
NetR78_2: R78.2 U9.5(XTAL1/CLKIN)
NetR84_1: R84.1 U9.24(RBIAS)

Not connected (* = marked no-connect by the designer): CN9 9(NC)*; U9 4(XTAL2)*

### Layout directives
differential pair: RD_N, RD_P, TD_N, TD_P
rule Matched Net Lengths [Tolerance = 100mil]: RD_N, RD_P, TD_N, TD_P

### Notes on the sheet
- LED2_SPEED_YELLOW
- LED1_LINK/ACT_GREEN

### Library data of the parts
C60 C74 C81-C83 = Cap_100nF_X7R_10%_0402: as C110 on sheet USB_OTG_HS
C63 C73 = Cap_10uF_POL_10%_TANA: Polarized Capacitor,10uF,10V,10%,typeA,VISHAY; Manuf_Part_1: 293D106X9010A2TE3
C66 = Cap_470pF_X7R_10%_0402: Capacitor,470pF,16V,X7R,10%,0402,YAGEO; Manuf_Part_1: 0402YC471KAT4A; Manuf_1: AVX
C67 = Cap_1uF_X5R_10%_0603: Capacitor,1uF,16V,X5R,10%,0603,YAGEO; Manuf_Part_1: CC0603KRX5R7BB105
CN9 = HR961160C: 100 Base-TX (Fast Ethernet) SMD RJ45 single port (1x1) with LEDS Integrated Magnetics Connector; Manuf_1: HanRun; Manuf_2: Pulse Electronics Corporation; Manuf_Part_2: J3011G21DNLT; Manuf_3: K.O.D International Holding; Manuf_Part_3: RMT-119A-12F6-GY-04
L2 = BEAD_120R_2A_0603: as L6 on sheet USB_OTG_HS
R65 = Res_1K5_1%_0402: Resistor,1K5,0402,1%,YAGEO; Manuf_Part_1: RC0402FR-071K5L
R66 R69 R71 = Res_33_1%_0402: Resistor,33,0402,1%,YAGEO; Manuf_Part_1: RC0402FR-0733RL
R67 R68 R70 R73 R77 = Res_4K7_1%_0402: Resistor,4K7,0402,1%,YAGEO; Manuf_Part_1: RT0402FRE074K7L
R78 = Res_100_1%_0402: as R29 on sheet STM32F7
R84 = Res_12K1_1%_0603: Resistor,12K1,0603,1%,VISHAY; Manuf_Part_1: MCT 0603-50 1% P5 12K1; Order: 2325243
R88 R95 = Res_10K_1%_0402: as R5 on sheet STM32F7
R89 R94 = Res_330_1%_0402: Resistor,330,0402,1%,YAGEO; Manuf_Part_1: RC0402FR-07330RL
R90-R93 = Res_50_1%_0402: Resistor,50,0402,1%,YAGEO; Manuf_Part_1: RC0402FR-0749R9L; Value: 49.9
U9 = LAN8742A-CZ-TR: LAN8742A-CZ-TR - Small Footprint RMII 10/100 Ethernet, Transceiver with HP Auto-MDIX and flexPWR Technology SQFN-24; Manuf_1: MICROCHIP

## Sheet Camera-Connectors.SchDoc: External Camera connector
size A4; Date: 25-FEB-2015; Author: A.B; CompanyName: STMicroelectronics; Address1: 12, Rue Jules HOROWITZ; Address2: 38019 Grenoble; Address3: FRANCE; DocumentNumber: MB1191; Revision: B-02; SheetNumber: 13; SheetTotal: 14; Project: STM32F746G-DISCO
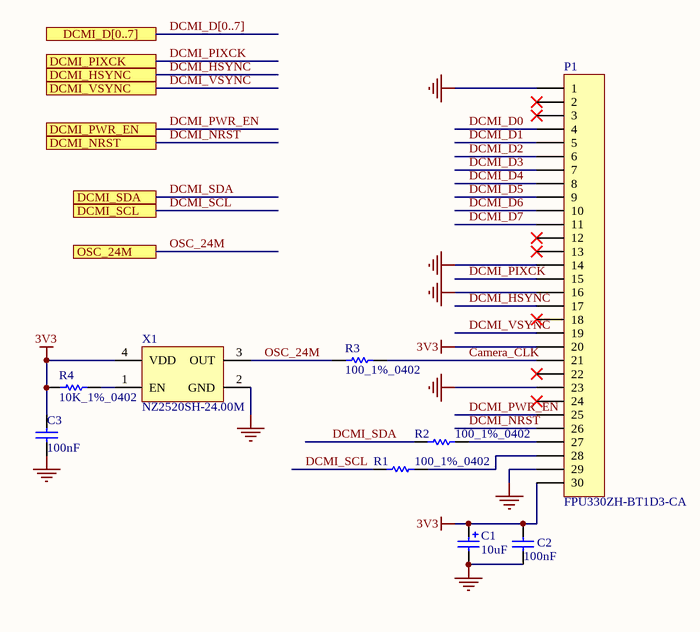
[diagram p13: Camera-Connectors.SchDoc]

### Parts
C1  10uF  [TAN-A]
C2  100nF  [0402C]
C3  100nF  [0402C]
P1  FPU330ZH-BT1D3-CA  [FPU330ZH-BT1D3-CA]
R1  100_1%_0402  [0402R]
R2  100_1%_0402  [0402R]
R3  100_1%_0402  [0402R]
R4  10K_1%_0402  [0402R]
X1  NZ2520SH-24.00M  [NZ2520SH_4P]

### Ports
DCMI_D[0..7], DCMI_HSYNC, DCMI_NRST, DCMI_PIXCK, DCMI_PWR_EN, DCMI_SCL, DCMI_SDA, DCMI_VSYNC, OSC_24M

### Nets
3V3: C1.1 C2.2 C3.2 P1.20 P1.30 R4.1 X1.4(VDD)
GND: C1.2 C2.1 C3.1 P1.1 P1.14 P1.16 P1.23 P1.29 X1.2(GND)
Camera_CLK: P1.21 R3.2
DCMI_D0: P1.4
DCMI_D1: P1.5
DCMI_D2: P1.6
DCMI_D3: P1.7
DCMI_D4: P1.8
DCMI_D5: P1.9
DCMI_D6: P1.10
DCMI_D7: P1.11
DCMI_HSYNC: P1.17 ; port DCMI_HSYNC
DCMI_NRST: P1.26 ; port DCMI_NRST
DCMI_PIXCK: P1.15 ; port DCMI_PIXCK
DCMI_PWR_EN: P1.25 ; port DCMI_PWR_EN
DCMI_SCL: R1.1 ; port DCMI_SCL  [project net ARD_D15]
DCMI_SDA: R2.1 ; port DCMI_SDA  [project net ARD_D14]
DCMI_VSYNC: P1.19 ; port DCMI_VSYNC
OSC_24M: R3.1 X1.3(OUT) ; port OSC_24M
NetP1_27: P1.27 R2.2
NetP1_28: P1.28 R1.2
NetR4_2: R4.2 X1.1(EN)

Not connected (* = marked no-connect by the designer): P1 2* 3* 12* 13* 18* 22* 24*

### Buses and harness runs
bus DCMI_D[0..7] = port DCMI_D[0..7]

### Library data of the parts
C1 = Cap_10uF_POL_10%_TANA: as C63 on sheet Ethernet
C2 C3 = Cap_100nF_X7R_10%_0402: as C110 on sheet USB_OTG_HS
P1 = FPU330ZH-BT1D3-CA: TOWNES -  Connector FFC/FPC ZIF 0.5mm 30 pins, Lower Contacts; Manuf_Part_2: TFP-A330ZH-BT1-ECX
R1-R3 = Res_100_1%_0402: as R114 on sheet USB_OTG_HS
R4 = Res_10K_1%_0402: as R5 on sheet STM32F7
X1 = OSC_24M_NZ2520SB: Oscillator 24.00Mhz, -+50PPM, 3.3V, Temp -55 to +125°C; Manuf_Part_1: NZ2520SH 24MHz END4869D; Manuf_1: NDK; ECCN_US/EU: EAR99/NEC; Provided: ST

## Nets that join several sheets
1V8: ST_LINK_V2-1 (C108.2 U13.2 U13.4), AUDIO (6 pins), USB_OTG_HS (C110.2 U15.28 U15.30)
3V3: ST_LINK_V2-1 (C68.2 C75.2 U7.4 U13.3), AUDIO (14 pins), USB_OTG_FS (R116.2 R126.2 R136.2 R137.2), Peripherals (9 pins), QSPI (C38.2 R57.2 U3.8), LCD-43 (5 pins), Arduino_ Connectors (CN6.2 CN6.4), SDRAM (28 pins), USB_OTG_HS (8 pins), STM32F7 (11 pins), Ethernet (17 pins), Camera-Connectors (7 pins)
5V: ST_LINK_V2-1 (10 pins), USB_OTG_FS (U16.5), Peripherals (SB2.2), Arduino_ Connectors (CN6.5), USB_OTG_HS (C117.1 U15.21 U17.5)
5V_USB_FS: ST_LINK_V2-1 (D3.1 JP1.5), USB_OTG_FS (SB18.1)
5V_USB_HS: ST_LINK_V2-1 (D4.1 JP1.7), USB_OTG_HS (CN12.1 D7.A1 L6.2)
GND: ST_LINK_V2-1 (46 pins), AUDIO (43 pins), USB_OTG_FS (7 pins), Peripherals (12 pins), QSPI (C38.1 U3.4), LCD-43 (8 pins), Arduino_ Connectors (5 pins), SDRAM (46 pins), USB_OTG_HS (22 pins), STM32F7 (54 pins), Ethernet (19 pins), Camera-Connectors (9 pins)
VDD: Peripherals (B1.1 B1.4), STM32F7 (43 pins)
VIN: ST_LINK_V2-1 (C29.2 U6.3), Arduino_ Connectors (CN6.8)
VREF+: Arduino_ Connectors (C90.2 R96.2), STM32F7 (C17.1 C24.2 R28.2 U5.P1)
ARD_A0: Arduino_ Connectors (CN5.1), STM32F7 (U5.N3)
ARD_A1: Arduino_ Connectors (CN5.2), STM32F7 (U5.L1)
ARD_A2: Arduino_ Connectors (CN5.3), STM32F7 (U5.L2)
ARD_A3: Arduino_ Connectors (CN5.4), STM32F7 (U5.L3)
ARD_A4: Arduino_ Connectors (SB5.1), STM32F7 (U5.K1)
ARD_A5: Arduino_ Connectors (SB3.1), STM32F7 (U5.K2)
ARD_D0: Arduino_ Connectors (CN4.1), STM32F7 (U5.G15)
ARD_D1: Arduino_ Connectors (CN4.2), STM32F7 (U5.H15)
ARD_D2: Arduino_ Connectors (CN4.3), STM32F7 (U5.J15)
ARD_D3: Arduino_ Connectors (CN4.4), STM32F7 (U5.A9)
ARD_D4: Arduino_ Connectors (CN4.5), STM32F7 (U5.J14)
ARD_D5: Arduino_ Connectors (CN4.6), STM32F7 (U5.E14)
ARD_D6: Arduino_ Connectors (CN4.7), STM32F7 (U5.P13)
ARD_D7: Arduino_ Connectors (CN4.8), STM32F7 (U5.C13)
ARD_D8: Arduino_ Connectors (CN7.1), STM32F7 (U5.C14)
ARD_D9: Arduino_ Connectors (CN7.2), STM32F7 (U5.A13)
ARD_D10: Arduino_ Connectors (CN7.3), STM32F7 (U5.F15)
ARD_D11: Arduino_ Connectors (CN7.4), STM32F7 (U5.R15)
ARD_D12: Arduino_ Connectors (CN7.5), STM32F7 (U5.R14)
ARD_D13: Arduino_ Connectors (CN7.6 SB8.2), STM32F7 (U5.D14)
ARD_D14: Peripherals (CN2.1), Arduino_ Connectors (CN7.9 SB4.1), STM32F7 (R46.1 U5.B4), Camera-Connectors (R2.1)
ARD_D15: Peripherals (CN2.3), Arduino_ Connectors (CN7.10 SB1.1), STM32F7 (R54.1 U5.A7), Camera-Connectors (R1.1)
Audio_INT: AUDIO (U11.G3), STM32F7 (U5.B11)
AUDIO_SCL: AUDIO (R76.1), LCD-43 (U19.39), STM32F7 (R62.1 U5.N13)
AUDIO_SDA: AUDIO (R83.1), LCD-43 (U19.40), STM32F7 (R61.1 U5.P14)
B_USER: Peripherals (SB6.1), STM32F7 (U5.F3)
DCMI_D0: STM32F7 (U5.N14), Camera-Connectors (P1.4)
DCMI_D1: STM32F7 (U5.P15), Camera-Connectors (P1.5)
DCMI_D2: STM32F7 (U5.N15), Camera-Connectors (P1.6)
DCMI_D3: STM32F7 (U5.M15), Camera-Connectors (P1.7)
DCMI_D4: STM32F7 (U5.E13), Camera-Connectors (P1.8)
DCMI_D5: STM32F7 (U5.C11), Camera-Connectors (P1.9)
DCMI_D6: STM32F7 (U5.B1), Camera-Connectors (P1.10)
DCMI_D7: STM32F7 (U5.B2), Camera-Connectors (P1.11)
DCMI_HSYNC: STM32F7 (U5.N4), Camera-Connectors (P1.17)
DCMI_NRST: ST_LINK_V2-1 (SB15.2), Peripherals (SB7.1), LCD-43 (U19.37), Arduino_ Connectors (CN6.3), USB_OTG_HS (U15.27), STM32F7 (R34.1 U5.J1), Ethernet (U9.15), Camera-Connectors (P1.26)
DCMI_PIXCK: STM32F7 (U5.P3), Camera-Connectors (P1.15)
DCMI_PWR_EN: STM32F7 (U5.E12), Camera-Connectors (P1.25)
DCMI_VSYNC: STM32F7 (U5.D9), Camera-Connectors (P1.19)
EXT_RST: Peripherals (CN2.4), STM32F7 (U5.M12)
FMC_A0: SDRAM (U4.G8), STM32F7 (U5.D2)
FMC_A1: SDRAM (U4.G9), STM32F7 (U5.E2)
FMC_A2: SDRAM (U4.F7), STM32F7 (U5.G2)
FMC_A3: SDRAM (U4.F3), STM32F7 (U5.H2)
FMC_A4: SDRAM (U4.G1), STM32F7 (U5.J2)
FMC_A5: SDRAM (U4.G2), STM32F7 (U5.K3)
FMC_A6: SDRAM (U4.G3), STM32F7 (U5.M6)
FMC_A7: SDRAM (U4.H1), STM32F7 (U5.N6)
FMC_A8: SDRAM (U4.H2), STM32F7 (U5.P6)
FMC_A9: SDRAM (U4.J3), STM32F7 (U5.M8)
FMC_A10: SDRAM (U4.G7), STM32F7 (U5.N7)
FMC_A11: SDRAM (U4.H9), STM32F7 (U5.M7)
FMC_BA0: SDRAM (U4.J7), STM32F7 (U5.N12)
FMC_BA1: SDRAM (U4.H8), STM32F7 (U5.N11)
FMC_D0: SDRAM (U4.R8), STM32F7 (U5.L12)
FMC_D1: SDRAM (U4.N7), STM32F7 (U5.K13)
FMC_D2: SDRAM (U4.R9), STM32F7 (U5.B12)
FMC_D3: SDRAM (U4.N8), STM32F7 (U5.C12)
FMC_D4: SDRAM (U4.P9), STM32F7 (U5.R8)
FMC_D5: SDRAM (U4.M8), STM32F7 (U5.N9)
FMC_D6: SDRAM (U4.M7), STM32F7 (U5.P9)
FMC_D7: SDRAM (U4.L8), STM32F7 (U5.R9)
FMC_D8: SDRAM (U4.L2), STM32F7 (U5.P10)
FMC_D9: SDRAM (U4.M3), STM32F7 (U5.R10)
FMC_D10: SDRAM (U4.M2), STM32F7 (U5.R12)
FMC_D11: SDRAM (U4.P1), STM32F7 (U5.P11)
FMC_D12: SDRAM (U4.N2), STM32F7 (U5.R11)
FMC_D13: SDRAM (U4.R1), STM32F7 (U5.L15)
FMC_D14: SDRAM (U4.N3), STM32F7 (U5.L14)
FMC_D15: SDRAM (U4.R2), STM32F7 (U5.K15)
FMC_NBL0: SDRAM (U4.K9), STM32F7 (U5.A6)
FMC_NBL1: SDRAM (U4.K1), STM32F7 (U5.A5)
FMC_SDCKE0: SDRAM (U4.J2), STM32F7 (U5.L4)
FMC_SDCLK: SDRAM (U4.J1), STM32F7 (U5.H14)
FMC_SDNCAS: SDRAM (U4.K7), STM32F7 (U5.B7)
FMC_SDNE0: SDRAM (U4.J8), STM32F7 (U5.J4)
FMC_SDNRAS: SDRAM (U4.J9), STM32F7 (U5.P8)
FMC_SDNWE: SDRAM (U4.K8), STM32F7 (U5.J3)
LCD_B0: LCD-43 (U19.21), STM32F7 (U5.A1)
LCD_B1: LCD-43 (U19.22), STM32F7 (U5.B9)
LCD_B2: LCD-43 (U19.23), STM32F7 (U5.C9)
LCD_B3: LCD-43 (U19.24), STM32F7 (U5.D10)
LCD_B4: LCD-43 (U19.25), STM32F7 (U5.C7)
LCD_B5: LCD-43 (U19.26), STM32F7 (U5.D7)
LCD_B6: LCD-43 (U19.27), STM32F7 (U5.C6)
LCD_B7: LCD-43 (U19.28), STM32F7 (U5.C5)
LCD_BL_CTRL: LCD-43 (R81.2), STM32F7 (U5.D8)
LCD_CLK: LCD-43 (U19.30), STM32F7 (U5.H3)
LCD_DE: LCD-43 (U19.34), STM32F7 (U5.C4)
LCD_DISP: LCD-43 (R74.1 U19.31), STM32F7 (U5.E3)
LCD_G0: LCD-43 (U19.13), STM32F7 (U5.J12)
LCD_G1: LCD-43 (U19.14), STM32F7 (U5.H12)
LCD_G2: LCD-43 (U19.15), STM32F7 (U5.J13)
LCD_G3: LCD-43 (U19.16), STM32F7 (U5.H13)
LCD_G4: LCD-43 (U19.17), STM32F7 (U5.G12)
LCD_G5: LCD-43 (U19.18), STM32F7 (U5.G13)
LCD_G6: LCD-43 (U19.19), STM32F7 (U5.F12)
LCD_G7: LCD-43 (U19.20), STM32F7 (U5.F13)
LCD_HSYNC: LCD-43 (U19.32), STM32F7 (U5.D5)
LCD_INT: LCD-43 (U19.38), STM32F7 (U5.G3)
LCD_R0: LCD-43 (U19.5), STM32F7 (U5.G4)
LCD_R1: LCD-43 (U19.6), STM32F7 (U5.R6)
LCD_R2: LCD-43 (U19.7), STM32F7 (U5.R7)
LCD_R3: LCD-43 (U19.8), STM32F7 (U5.P7)
LCD_R4: LCD-43 (U19.9), STM32F7 (U5.N8)
LCD_R5: LCD-43 (U19.10), STM32F7 (U5.M9)
LCD_R6: LCD-43 (U19.11), STM32F7 (U5.M14)
LCD_R7: LCD-43 (U19.12), STM32F7 (U5.K12)
LCD_VSYNC: LCD-43 (U19.33), STM32F7 (U5.E4)
OSC_24M: USB_OTG_HS (R114.1), Camera-Connectors (R3.1 X1.3)
OSC_25M: STM32F7 (R30.1 X2.3), Ethernet (R78.1)
OTG_FS_ID: USB_OTG_FS (R133.1), STM32F7 (U5.D15)
OTG_FS_N: USB_OTG_FS (R132.1 U18.D3), STM32F7 (U5.C15)
OTG_FS_OverCurrent: USB_OTG_FS (R119.2), STM32F7 (U5.D11)
OTG_FS_P: USB_OTG_FS (R125.1 U18.C3), STM32F7 (U5.B15)
OTG_FS_PowerSwitchOn: USB_OTG_FS (R117.1), STM32F7 (U5.C10)
OTG_FS_VBUS: USB_OTG_FS (6 pins), STM32F7 (R58.2 R63.1)
OTG_HS_OverCurrent: USB_OTG_HS (R130.2), STM32F7 (U5.A2)
PA1: STM32F7 (U5.N2), Ethernet (R77.1 U9.14)
PA2: STM32F7 (U5.P2), Ethernet (R65.1 U9.12)
PA3: USB_OTG_HS (U15.3), STM32F7 (U5.R2)
PA5: USB_OTG_HS (U15.1), STM32F7 (U5.P4)
PA7: STM32F7 (U5.R3), Ethernet (R66.2)
PA13: ST_LINK_V2-1 (SB17.2), STM32F7 (U5.A15)
PA14: ST_LINK_V2-1 (SB14.2), STM32F7 (U5.A14)
PB0: USB_OTG_HS (U15.4), STM32F7 (U5.R5)
PB1: USB_OTG_HS (U15.5), STM32F7 (U5.R4)
PB2: QSPI (U3.6), STM32F7 (R44.1)
PB3: ST_LINK_V2-1 (SB16.2), STM32F7 (U5.A10)
PB5: USB_OTG_HS (U15.13), STM32F7 (U5.A8)
PB6: QSPI (R57.1 U3.1), STM32F7 (U5.B6)
PB7: ST_LINK_V2-1 (SB12.1), STM32F7 (U5.B5)
PB10: USB_OTG_HS (U15.6), STM32F7 (U5.P12)
PB11: USB_OTG_HS (U15.7), STM32F7 (U5.R13)
PB12: USB_OTG_HS (U15.9), STM32F7 (U5.L13)
PB13: USB_OTG_HS (U15.10), STM32F7 (U5.K14)
PC0: USB_OTG_HS (U15.29), STM32F7 (U5.M2)
PC1: STM32F7 (U5.M3), Ethernet (U9.13)
PC2: USB_OTG_HS (U15.31), STM32F7 (U5.M4)
PC4: STM32F7 (U5.N5), Ethernet (R69.2)
PC5: STM32F7 (U5.P5), Ethernet (R71.2)
PC8: Peripherals (CN3.7 R14.1), STM32F7 (U5.G14)
PC9: Peripherals (CN3.8 R13.1), STM32F7 (U5.F14)
PC10: Peripherals (CN3.1 R17.1), STM32F7 (U5.B14)
PC11: Peripherals (CN3.2 R16.1), STM32F7 (U5.B13)
PC12: Peripherals (CN3.5), STM32F7 (U5.A12)
PC13: Peripherals (R11.1 R12.1), STM32F7 (U5.D1)
PD2: Peripherals (CN3.3 R15.1), STM32F7 (U5.D12)
PD7: AUDIO (R8.2 R22.2 U2.4), STM32F7 (U5.A11)
PD11: QSPI (U3.5), STM32F7 (U5.N10)
PD12: QSPI (U3.2), STM32F7 (U5.M10)
PD13: QSPI (U3.7), STM32F7 (U5.M11)
PE2: QSPI (U3.3), STM32F7 (U5.A3)
PG2: STM32F7 (U5.M13), Ethernet (R68.2 U9.10)
PG10: AUDIO (U11.F2), STM32F7 (U5.C8)
PG11: STM32F7 (U5.B8), Ethernet (U9.16)
PG13: STM32F7 (U5.B3), Ethernet (U9.17)
PG14: STM32F7 (U5.A4), Ethernet (U9.18)
PH4: USB_OTG_HS (U15.2), STM32F7 (U5.H4)
PH15: AUDIO (TP3.1), STM32F7 (U5.D13)
PI4: AUDIO (U11.D3), STM32F7 (U5.C3)
PI5: AUDIO (U11.G1), STM32F7 (U5.D3)
PI6: AUDIO (U11.E4), STM32F7 (U5.D6)
PI7: AUDIO (U11.E3), STM32F7 (U5.D4)
VCP_TX: ST_LINK_V2-1 (SB13.1), STM32F7 (R64.1)

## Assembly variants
F746NGH6: not fitted C90 CN8 JP3 JP4 R8 R12 R35 R42 R63 R80 R100 R103 R106 R109 R111
F750N8H6: not fitted C90 CN8 JP3 JP4 R8 R12 R35 R42 R63 R80 R100 R103 R106 R109 R111; alternate parts U5 -> STM32F750N8H6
